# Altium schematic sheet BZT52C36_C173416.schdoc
size 127 x 101 mm
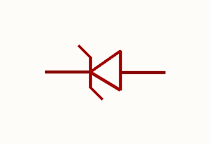
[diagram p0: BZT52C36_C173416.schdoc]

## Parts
D?  bzt52c36_c173416  [SOD-123_L2.7-W1.6-LS3.7-RD]  (value not drawn)

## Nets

Not connected (* = marked no-connect by the designer): D? 1(C) 2(A)

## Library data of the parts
D? = bzt52c36_c173416: 二极管配置:1个独立式;稳压值(标称值):36V;稳压值(范围):34.2V~37.8V;耗散功率(Pd):500mW;; Manufacturer: MDD(辰达半导体); AddInBom: yes; ModelId: ad7e39f9e5534b3c96ffdc5532ebb493; ModelName: SOD-123_L2.7-W1.6-H1.4-LS3.7; ModelTransform: 146.026,62.992,0,180,0,0,0.0005,0,0; Diode Configuration: 1个独立式; Zener Voltage(Nom): 36V; Reverse Leakage Current (Ir): 100nA@27V; Pd - Power Dissipation: 500mW; Impedance(Zzt): 90Ω; Tolerance: ±5%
